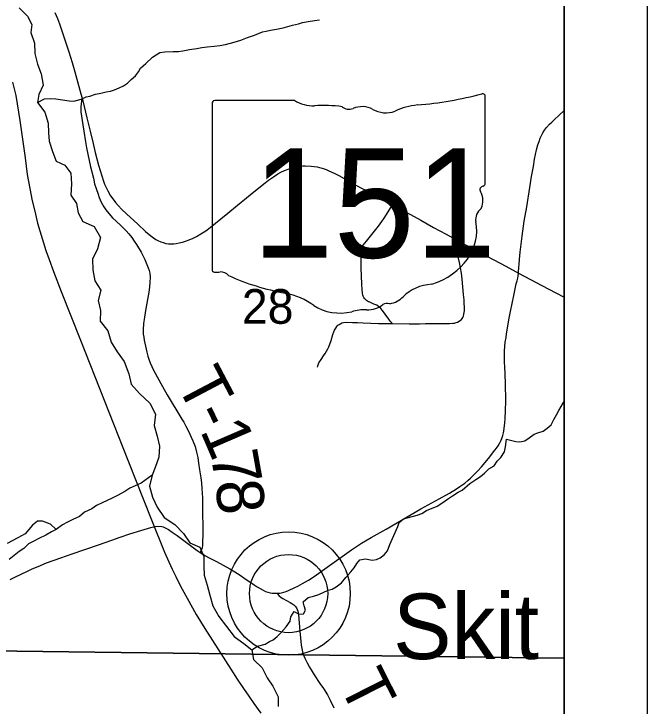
# Model space of a CAD drawing. Extents: x 0 to 34, y 0 to 22.
# Drawn here: x 16.736 to 17.5, y 15.839 to 16.673 of the extents above; entities that cross this region are included whole.
import ezdxf

# ---------------------------------------------------------------- set-up
doc = ezdxf.new("R2010")
doc.units = 0
for name, color, linetype in [('GM_X_Corporation', 7, 'Continuous'), ('GM_X_County_Road', 7, 'Continuous'), ('GM_X_Major_River', 7, 'Continuous'), ('GM_X_Minor_River', 7, 'Continuous'), ('GM_X_Rail_Line', 7, 'Continuous'), ('GM_X_Section_Text', 7, 'Continuous'), ('GM_X_State_Location', 7, 'Continuous'), ('GM_X_State_Route', 7, 'Continuous'), ('GM_X_State_Shield', 7, 'Continuous'), ('GM_X_Township_Road', 7, 'Continuous'), ('GM_X_Township_Road_Text', 7, 'Continuous'), ('GM_X_Unincorporated', 7, 'Continuous'), ('GM_X_Unincorporated_Location', 7, 'Continuous'), ('GM_X_Unincorporated_Text', 7, 'Continuous'), ('SH_Data', 7, 'Continuous')]:
    doc.layers.add(name, color=color, linetype=linetype)

msp = doc.modelspace()

# ---------------------------------------------------------------- linework, layer by layer
at = {"layer": 'GM_X_Corporation'}
for points in [[(16.42143, 13.6), (17.4, 13.6), (17.4, 16.91301), (16.55155, 16.92431), (16.46891, 16.92454), (16.46029, 16.26174), (16.46108, 16.1288), (16.45161, 15.59641), (16.44975, 15.46263), (16.44192, 14.8642), (16.438, 14.59078), (16.43392, 14.38059), (16.42123, 13.66087)], [(17.4, 15.89665), (17.4, 16.91338), (16.46597, 16.92627), (16.46598, 16.92141), (16.45629, 15.90843)], [(17.4, 14.8906), (17.4, 15.89665), (16.45629, 15.90843), (16.44101, 14.88556)]]:
    msp.add_lwpolyline(points, close=True, dxfattribs=at)
at = {"layer": 'GM_X_County_Road'}
for points in [[(17.34462, 16.36077), (17.3448, 16.36271), (17.3452, 16.36697), (17.34553, 16.37175), (17.34603, 16.37726), (17.34673, 16.38598), (17.34906, 16.40527), (17.3518, 16.42351), (17.35476, 16.44079), (17.3584, 16.46396), (17.36055, 16.4773), (17.3627, 16.48912), (17.36409, 16.49806), (17.36646, 16.5094), (17.36821, 16.51528), (17.36953, 16.5195), (17.37106, 16.52334), (17.37251, 16.5265), (17.37427, 16.52968), (17.37631, 16.53292), (17.37861, 16.5361), (17.38215, 16.54011), (17.38492, 16.54288), (17.38769, 16.54558), (17.4, 16.55658)], [(17.05349, 15.97466), (17.05498, 15.97474), (17.05687, 15.97497), (17.05903, 15.97539), (17.0644, 15.97698), (17.06744, 15.97813), (17.07505, 15.98153), (17.07873, 15.98341), (17.08438, 15.98651), (17.09128, 15.99057), (17.09931, 15.99567), (17.10566, 16.00001), (17.11698, 16.00818), (17.14334, 16.02718), (17.15545, 16.03493), (17.16698, 16.04194), (17.18507, 16.05219), (17.22703, 16.07633), (17.24891, 16.08843), (17.26161, 16.09551), (17.27017, 16.1007), (17.2742, 16.10335), (17.27641, 16.10489), (17.28008, 16.10758), (17.2837, 16.1106), (17.28688, 16.11341), (17.2927, 16.11913), (17.29587, 16.12248), (17.30016, 16.12713), (17.30861, 16.13738), (17.31643, 16.14712), (17.31823, 16.14948), (17.32025, 16.15256), (17.3223, 16.15595), (17.32349, 16.1585), (17.32479, 16.16135), (17.32605, 16.16499), (17.32683, 16.16819), (17.32722, 16.17026), (17.3284, 16.18022), (17.32878, 16.18499), (17.32911, 16.19492), (17.32935, 16.20626), (17.32899, 16.22808), (17.32824, 16.24832), (17.32803, 16.25262), (17.32793, 16.25808), (17.32804, 16.26716), (17.3289, 16.27733), (17.32981, 16.28323), (17.33048, 16.28743), (17.33368, 16.30637), (17.33529, 16.31457), (17.33909, 16.33381), (17.34197, 16.34768), (17.34316, 16.35155), (17.34387, 16.35459), (17.34432, 16.3572), (17.34462, 16.36077)], [(16.73158, 15.99118), (16.73726, 15.99418), (16.75247, 16.00142), (16.75828, 16.00404), (16.76524, 16.0071), (16.77542, 16.01127), (16.79256, 16.0175), (16.80652, 16.02237), (16.8383, 16.03328), (16.85401, 16.03884), (16.86434, 16.04243), (16.87598, 16.04633), (16.88926, 16.05056), (16.9013, 16.05406), (16.90636, 16.05514), (16.90943, 16.05552), (16.91468, 16.05518), (16.91617, 16.05465), (16.91779, 16.05398), (16.9203, 16.05278), (16.92265, 16.05141), (16.92709, 16.04848), (16.93295, 16.04418), (16.9556, 16.02743), (16.9584, 16.02551), (16.96087, 16.02387)], [(16.96087, 16.02387), (16.9671, 16.01997), (16.97099, 16.01781), (16.98036, 16.01284), (16.99651, 16.00427), (17.00277, 16.0006), (17.00885, 15.99668), (17.01347, 15.99351), (17.02572, 15.9848), (17.02936, 15.98259), (17.03305, 15.98039), (17.03668, 15.97844), (17.03966, 15.97703), (17.04236, 15.97604), (17.04511, 15.97536), (17.04753, 15.97498), (17.05156, 15.97467), (17.05349, 15.97466)]]:
    msp.add_lwpolyline(points, dxfattribs=at)
at = {"layer": 'GM_X_Major_River'}
for points in [[(16.74262, 16.68064), (16.75263, 16.67053), (16.7577, 16.66036), (16.7563, 16.65085), (16.76103, 16.63801), (16.76119, 16.62549), (16.7644, 16.61263), (16.76911, 16.60093), (16.77156, 16.58731), (16.76602, 16.57585), (16.76463, 16.56634), (16.77351, 16.5547), (16.77748, 16.54147), (16.77764, 16.52971), (16.77852, 16.51985), (16.78249, 16.50739), (16.78719, 16.49569), (16.79751, 16.49089), (16.80485, 16.48113), (16.8054, 16.46823), (16.80482, 16.45456), (16.81178, 16.44479), (16.81345, 16.43343), (16.81928, 16.42288), (16.83303, 16.417), (16.84041, 16.40382), (16.8368, 16.39011), (16.83089, 16.3775), (16.83144, 16.36461), (16.83389, 16.35136), (16.84087, 16.34007), (16.83762, 16.3275), (16.84043, 16.31578), (16.84022, 16.30287), (16.84949, 16.29123), (16.85346, 16.27762), (16.86083, 16.26596), (16.86895, 16.25431), (16.87484, 16.23921), (16.87767, 16.22672), (16.88768, 16.21547), (16.89998, 16.20388), (16.90699, 16.19069), (16.90527, 16.177), (16.90886, 16.16415)], [(16.90886, 16.16415), (16.91167, 16.15204), (16.91071, 16.13875), (16.90631, 16.12654), (16.90302, 16.11701), (16.89978, 16.10368), (16.90337, 16.09045), (16.90884, 16.07838), (16.91735, 16.06597), (16.93037, 16.05742), (16.94076, 16.04693), (16.9485, 16.03565), (16.96034, 16.03012), (16.96504, 16.01918), (16.9652, 16.00742), (16.96572, 15.99642), (16.96929, 15.98432), (16.97248, 15.9726), (16.97607, 15.95974), (16.98345, 15.94656), (16.99234, 15.93453), (17.00161, 15.92252), (17.01349, 15.91395), (17.02308, 15.90649), (17.02513, 15.89475), (17.03551, 15.88464), (17.04175, 15.87258), (17.04833, 15.8628), (17.05495, 15.84999), (17.05472, 15.83822)]]:
    msp.add_lwpolyline(points, dxfattribs=at)
at = {"layer": 'GM_X_Minor_River'}
for points in [[(16.76463, 16.56634), (16.77318, 16.57094), (16.78075, 16.57107), (16.78682, 16.5708), (16.7948, 16.5698), (16.80278, 16.56842), (16.80847, 16.56813), (16.81715, 16.57056), (16.82317, 16.57332), (16.8277, 16.57416), (16.83448, 16.57656), (16.8409, 16.57781), (16.84732, 16.57944), (16.85262, 16.57991), (16.85752, 16.58152), (16.86316, 16.58389), (16.86842, 16.58664), (16.87292, 16.58976), (16.8774, 16.59402), (16.88262, 16.59867), (16.88633, 16.60329), (16.88891, 16.60789), (16.89526, 16.61332), (16.90309, 16.62105), (16.91209, 16.62652), (16.91814, 16.62739), (16.92837, 16.62795), (16.93443, 16.62805), (16.93973, 16.62852), (16.94804, 16.63018), (16.95673, 16.63147), (16.96278, 16.63272), (16.96921, 16.63359), (16.97753, 16.63449), (16.98434, 16.63499), (16.99114, 16.63624), (17.00171, 16.63909), (17.00963, 16.6415), (17.01791, 16.64468), (17.0262, 16.64749), (17.03599, 16.65145), (17.04052, 16.65229), (17.04543, 16.65351), (17.05299, 16.65478), (17.06092, 16.65644), (17.07224, 16.65967), (17.07941, 16.66132), (17.08431, 16.66292), (17.09111, 16.66418), (17.09867, 16.66545), (17.10473, 16.66593)], [(17.02308, 15.90649), (17.02996, 15.9109), (17.03901, 15.91333), (17.04427, 15.91646), (17.04878, 15.91844), (17.05364, 15.9227), (17.05849, 15.92735), (17.06443, 15.93429), (17.06924, 15.94121), (17.0703, 15.94616), (17.07398, 15.95269), (17.07972, 15.94937), (17.08539, 15.94984), (17.08797, 15.95445), (17.08637, 15.95936), (17.08515, 15.96428), (17.09112, 15.9697), (17.09754, 15.97133), (17.10395, 15.97334), (17.11523, 15.97847), (17.12014, 15.97969), (17.12502, 15.98244), (17.13138, 15.98749), (17.13658, 15.99365), (17.14253, 16.0006), (17.14662, 16.00522), (17.14994, 16.0106), (17.15327, 16.01521), (17.16008, 16.01609), (17.16806, 16.01471), (17.17335, 16.01556), (17.17787, 16.01754), (17.18274, 16.02104), (17.18682, 16.02605), (17.18973, 16.03332), (17.19447, 16.04442), (17.19922, 16.05514), (17.20103, 16.06011), (17.20588, 16.06437), (17.22248, 16.06883), (17.22814, 16.07083), (17.23376, 16.07434), (17.24655, 16.07988), (17.25368, 16.08418), (17.2593, 16.08808), (17.2653, 16.09198), (17.27204, 16.09665), (17.27693, 16.09902), (17.28627, 16.10716), (17.29339, 16.11184), (17.29902, 16.11535), (17.30387, 16.11961), (17.3091, 16.12464), (17.31547, 16.12855), (17.31917, 16.13393), (17.32364, 16.13857), (17.32808, 16.1451), (17.32911, 16.1512), (17.33047, 16.16034), (17.33656, 16.15892), (17.34151, 16.15749), (17.34645, 16.15719), (17.35249, 16.15844), (17.35774, 16.16195), (17.36372, 16.16661), (17.36824, 16.16821), (17.37465, 16.17021), (17.37952, 16.17372), (17.384, 16.17797), (17.38731, 16.18411), (17.39062, 16.18986), (17.39356, 16.19523), (17.39614, 16.19983), (17.39908, 16.20482), (17.4, 16.20592)], [(16.90302, 16.11701), (16.88943, 16.10757), (16.88228, 16.10441), (16.87589, 16.10126), (16.8699, 16.09735), (16.86201, 16.09304), (16.85449, 16.08949), (16.84847, 16.08673), (16.84246, 16.08359), (16.83569, 16.08043), (16.83007, 16.07653), (16.82142, 16.07259), (16.81507, 16.06716), (16.80717, 16.0636), (16.80078, 16.06045), (16.79477, 16.05731), (16.78691, 16.05148), (16.78127, 16.04872), (16.77452, 16.0448), (16.76624, 16.04086), (16.76024, 16.03734), (16.75385, 16.03419), (16.74788, 16.02877), (16.74226, 16.02487), (16.73029, 16.01555)], [(16.78691, 16.05148), (16.78035, 16.0582), (16.77044, 16.06183), (16.76437, 16.06173), (16.7584, 16.05668), (16.74947, 16.04627), (16.74084, 16.04156), (16.72806, 16.03489)]]:
    msp.add_lwpolyline(points, dxfattribs=at)
at = {"layer": 'GM_X_Rail_Line'}
msp.add_lwpolyline([(16.73436, 16.59103), (16.73822, 16.57482), (16.74336, 16.54454), (16.74948, 16.49966), (16.75226, 16.47959), (16.75519, 16.46261), (16.75828, 16.4478), (16.76121, 16.43529), (16.76461, 16.42079), (16.77188, 16.39736), (16.77464, 16.38791), (16.7785, 16.37726), (16.78375, 16.3626), (16.79316, 16.33852), (16.81632, 16.27971), (16.87358, 16.13509), (16.90213, 16.06317), (16.91772, 16.02427), (16.92281, 16.01269), (16.92698, 16.0039), (16.9313, 15.99479), (16.93701, 15.98337), (16.94489, 15.96871), (16.956, 15.94926), (16.96634, 15.93243), (16.99783, 15.88335), (17.00539, 15.87116), (17.01295, 15.86005), (17.01944, 15.85063), (17.02561, 15.84168), (17.0341, 15.83026)], dxfattribs=at)
at = {"layer": 'GM_X_State_Route'}
msp.add_lwpolyline([(16.78541, 16.67497), (16.78848, 16.6675), (16.7909, 16.66117), (16.79424, 16.65172), (16.80222, 16.62758), (16.80634, 16.61453), (16.8096, 16.60343), (16.81697, 16.57671), (16.81835, 16.57147), (16.82091, 16.56151), (16.82424, 16.548), (16.82818, 16.53171), (16.83163, 16.51694), (16.83422, 16.50627), (16.83817, 16.49073), (16.84009, 16.48428), (16.8441, 16.47154), (16.84553, 16.46797), (16.84805, 16.46235), (16.84933, 16.45994), (16.85278, 16.45404), (16.85537, 16.45011), (16.85854, 16.44591), (16.86183, 16.44221), (16.86633, 16.43747), (16.87197, 16.43221), (16.88563, 16.41955), (16.895, 16.41092), (16.90121, 16.40562), (16.90431, 16.40319), (16.90744, 16.40113), (16.90986, 16.39983), (16.91313, 16.3984), (16.91596, 16.39741), (16.91939, 16.39654), (16.92248, 16.3961), (16.9259, 16.39594), (16.92909, 16.39605), (16.93189, 16.39638), (16.93534, 16.39702), (16.93948, 16.39801), (16.94325, 16.39913), (16.94744, 16.40068), (16.95233, 16.40286), (16.95646, 16.40498), (16.96176, 16.40807), (16.96744, 16.4116), (16.97275, 16.41553), (16.98577, 16.42606), (16.99412, 16.43299), (17.00598, 16.44274), (17.01663, 16.45152), (17.02542, 16.45889), (17.03935, 16.4697), (17.04328, 16.47263), (17.04904, 16.47671), (17.05461, 16.48026), (17.05814, 16.48224), (17.06244, 16.48429), (17.06706, 16.48614), (17.07132, 16.48751), (17.07516, 16.48845), (17.07956, 16.4893), (17.08476, 16.48994), (17.08758, 16.49008), (17.09477, 16.4898), (17.10191, 16.48873), (17.10477, 16.48809), (17.10813, 16.48713), (17.11292, 16.48548), (17.11617, 16.48416), (17.12231, 16.48132), (17.12905, 16.47781), (17.13946, 16.47215), (17.15391, 16.46401), (17.16865, 16.45615), (17.19253, 16.44306), (17.20597, 16.43585), (17.21437, 16.43135), (17.22701, 16.42443), (17.2423, 16.41584), (17.25737, 16.40764), (17.27424, 16.39848), (17.2755, 16.39781), (17.3049, 16.382), (17.31508, 16.37656), (17.32934, 16.36896), (17.34462, 16.36077), (17.38054, 16.3419), (17.4, 16.33154)], dxfattribs=at)
at = {"layer": 'GM_X_State_Shield'}
for p, q in [((17.07492, 16.56875), (16.9784, 16.56875)), ((17.30474, 16.46903), (17.30474, 16.57371)), ((16.97516, 16.56531), (16.97516, 16.36519)), ((17.30471, 16.46905), (17.30474, 16.46903))]:
    msp.add_line(p, q, dxfattribs=at)
for centre, major_axis, start_param, end_param in [((17.18734, 16.84158), (0.34952, 0), 4.814394, 5.042369), ((17.30109, 16.57414), (0.00367, 0), 6.141152, 7.989035), ((16.97893, 16.56573), (0.00382, 0), 1.712693, 3.28349), ((17.09791, 16.59198), (0.03703, 0), 4.042523, 4.731795), ((17.11019, 16.4564), (0.13295, 0), 1.404758, 1.657858), ((17.14037, 16.56677), (0.01068, 0), 3.836095, 5.185415), ((17.15606, 16.54364), (0.02221, 0), 0.950623, 2.079405), ((17.23192, 16.50763), (0.07032, 0), 1.699011, 2.107814), ((17.18473, 16.57537), (0.02672, 0), 4.081561, 5.145723), ((17.30083, 16.46862), (0.00393, 0), 5.05454, 6.418171), ((17.30389, 16.46134), (0.00568, 0), 1.883978, 3.671073), ((17.26777, 16.44811), (0.03409, 0), 5.934695, 6.695948), ((17.31789, 16.42522), (0.0248, 0), 2.387724, 3.262537), ((17.20692, 16.4119), (0.08742, 0), 5.101752, 6.440018), ((16.97897, 16.36475), (0.00385, 0), 3.00124, 4.508301), ((16.97955, 16.38522), (0.0294, 0), 4.665946, 4.897461), ((16.98557, 16.35364), (0.0106, 0), 0.519207, 1.627899), ((17.11939, 16.53344), (0.2524, 0), 4.195997, 4.488961), ((17.24378, 16.309), (0.04788, 0), 1.647645, 2.488434), ((17.04414, 16.27528), (0.07897, 0), 0.823519, 1.323587), ((17.18312, 16.34579), (0.02824, 0), 4.937069, 5.64225), ((17.12955, 16.35265), (0.05011, 0), 4.026481, 4.996735), ((17.16217, 16.33766), (0.0267, 0), 4.691044, 5.507374), ((17.18632, 16.31828), (0.00752, 0), 1.147584, 2.315152), ((17.15851, 16.28346), (0.04118, 0), 1.495662, 1.94098)]:
    msp.add_ellipse(centre, major_axis=major_axis, ratio=0.8, start_param=start_param, end_param=end_param, dxfattribs=at)
at = {"layer": 'GM_X_Township_Road'}
for points in [[(16.81835, 16.57147), (16.81781, 16.56968), (16.81744, 16.56747), (16.81707, 16.56524), (16.81666, 16.56087), (16.81699, 16.55527), (16.81922, 16.5396), (16.82051, 16.53181), (16.82248, 16.51899), (16.82378, 16.51158), (16.82848, 16.48879), (16.83189, 16.47507), (16.83348, 16.46851), (16.83512, 16.46285), (16.83756, 16.45577), (16.83893, 16.45177), (16.84127, 16.44628), (16.84453, 16.44068), (16.84682, 16.43698), (16.85042, 16.4326), (16.85512, 16.42749), (16.86469, 16.41845), (16.87157, 16.41182), (16.87472, 16.40821), (16.87819, 16.4038), (16.8813, 16.3994), (16.88397, 16.39528), (16.88955, 16.38589), (16.89202, 16.38129), (16.8941, 16.37697), (16.89571, 16.37311), (16.8982, 16.36691), (16.89913, 16.36399), (16.89995, 16.36058), (16.90044, 16.35555), (16.90021, 16.34972), (16.89958, 16.34357), (16.89868, 16.33771), (16.89489, 16.3155), (16.89316, 16.30474), (16.8925, 16.29993), (16.89188, 16.29222), (16.89214, 16.2869), (16.89263, 16.28346), (16.89333, 16.27974), (16.89647, 16.2654), (16.89771, 16.26069), (16.89891, 16.2569), (16.90064, 16.25239), (16.90258, 16.24801), (16.9046, 16.24376), (16.91522, 16.22418), (16.92105, 16.21399), (16.93854, 16.18461), (16.94091, 16.18099), (16.94348, 16.17615), (16.94615, 16.17086), (16.95188, 16.15836), (16.9548, 16.15149), (16.95653, 16.14482), (16.95791, 16.1383), (16.9589, 16.13167), (16.96013, 16.12372), (16.96161, 16.11387), (16.96227, 16.10804), (16.9628, 16.10094), (16.96339, 16.08958), (16.96359, 16.07742), (16.96404, 16.04926), (16.9637, 16.03259), (16.96301, 16.02964), (16.96232, 16.02746), (16.96087, 16.02387)], [(17.19258, 16.29982), (17.19152, 16.30099), (17.18993, 16.30291), (17.18825, 16.30512), (17.18401, 16.31121), (17.1807, 16.31578), (17.17878, 16.3179), (17.17637, 16.32015), (17.17375, 16.32187), (17.17045, 16.32346), (17.16534, 16.3255), (17.16378, 16.32616), (17.16264, 16.32681), (17.1615, 16.32767), (17.16047, 16.32859), (17.15917, 16.32994), (17.1581, 16.33139), (17.15741, 16.33277), (17.15692, 16.33425), (17.15647, 16.33666), (17.15605, 16.34112), (17.15574, 16.34718), (17.15517, 16.36722), (17.1551, 16.38448), (17.15521, 16.38731), (17.15551, 16.38985), (17.15639, 16.39234), (17.15745, 16.39421), (17.16129, 16.39912), (17.17602, 16.41746), (17.17996, 16.42281), (17.18285, 16.42691), (17.18764, 16.43478), (17.19071, 16.43987), (17.19253, 16.44306)], [(17.10233, 16.24737), (17.10283, 16.24908), (17.10408, 16.25234), (17.10664, 16.25674), (17.10964, 16.26092), (17.11156, 16.26371), (17.11487, 16.26942), (17.11607, 16.27198), (17.11868, 16.2794), (17.12081, 16.2867), (17.12193, 16.28987), (17.12297, 16.29209), (17.12423, 16.29427), (17.12569, 16.29641), (17.12697, 16.29775), (17.12848, 16.29892), (17.13027, 16.3), (17.13175, 16.30067), (17.13349, 16.30116), (17.13709, 16.30145), (17.14438, 16.30136), (17.1506, 16.30099), (17.15748, 16.30061), (17.17582, 16.3001), (17.19258, 16.29982), (17.21298, 16.29969), (17.22541, 16.29975), (17.23268, 16.29985), (17.24467, 16.29991), (17.26142, 16.30007), (17.2654, 16.30027), (17.26776, 16.30054), (17.26967, 16.30102), (17.27132, 16.30166), (17.27341, 16.30278), (17.27495, 16.30387), (17.2759, 16.30481), (17.27669, 16.30584), (17.27749, 16.30707), (17.27831, 16.30871), (17.27901, 16.31101), (17.27948, 16.31518), (17.27906, 16.32831), (17.27858, 16.33481), (17.27677, 16.35328), (17.27587, 16.36059), (17.27356, 16.37352), (17.2724, 16.37887), (17.27178, 16.38417), (17.27166, 16.38726), (17.27189, 16.38948), (17.27288, 16.39247), (17.27414, 16.39512), (17.2755, 16.39781)], [(16.96087, 16.02387), (16.9671, 16.01997), (16.97099, 16.01781), (16.98036, 16.01284), (16.99651, 16.00427), (17.00277, 16.0006), (17.00885, 15.99668), (17.01347, 15.99351), (17.02572, 15.9848), (17.02936, 15.98259), (17.03305, 15.98039), (17.03668, 15.97844), (17.03966, 15.97703), (17.04236, 15.97604), (17.04511, 15.97536), (17.04753, 15.97498), (17.05156, 15.97467), (17.05349, 15.97466)], [(17.05349, 15.97466), (17.05404, 15.9739), (17.05567, 15.97207), (17.05851, 15.96976), (17.06052, 15.96855), (17.06925, 15.96373), (17.07145, 15.96238), (17.07367, 15.96061), (17.07535, 15.95896), (17.07679, 15.95711), (17.07782, 15.95532), (17.07868, 15.95329), (17.07917, 15.95129), (17.0795, 15.94904), (17.08108, 15.92865), (17.08203, 15.91697), (17.08265, 15.91201), (17.08364, 15.90608), (17.08476, 15.90223), (17.08701, 15.89639), (17.08972, 15.89096), (17.0925, 15.88572), (17.09583, 15.88034), (17.09826, 15.8765), (17.10516, 15.86611), (17.10966, 15.85984), (17.11445, 15.85244), (17.11766, 15.84594), (17.12197, 15.83677)]]:
    msp.add_lwpolyline(points, dxfattribs=at)
at = {"layer": 'GM_X_Unincorporated'}
for radius in [0.0744, 0.04716]:
    msp.add_circle((17.06746, 15.97431), radius, dxfattribs=at)
at = {"layer": 'GM_X_Unincorporated_Location'}
msp.add_line((17.06746, 15.97431), (17.06746, 15.97431), dxfattribs=at)
at = {"layer": 'SH_Data'}
for points in [[(10.5, 20.5), (17.5, 20.5), (17.5, 13.5), (10.5, 13.5)], [(10.6, 20.4), (17.4, 20.4), (17.4, 13.6), (10.6, 13.6)]]:
    msp.add_lwpolyline(points, close=True, dxfattribs=at)

# ---------------------------------------------------------------- texts
at = {"layer": 'GM_X_Section_Text'}
msp.add_text('28', height=0.041856, rotation=0.00001, dxfattribs=at).set_placement((17.01105, 16.29961))
at = {"layer": 'GM_X_State_Location'}
for s, p in [('s', (17.13625, 16.45194)), ('r', (17.13624, 16.45194))]:
    msp.add_text(s, height=0.000189, dxfattribs=at).set_placement(p)
msp.add_text('151', height=0.000189, rotation=0.00001, dxfattribs=at).set_placement((17.06939, 16.43816))
at = {"layer": 'GM_X_State_Shield'}
msp.add_text('151', height=0.131836, dxfattribs=at).set_placement((17.02372, 16.3793))
at = {"layer": 'GM_X_Township_Road_Text'}
for s, rotation, p in [('T', 297.8127, (16.93083, 16.22834)), ('-', 295.92561, (16.95039, 16.19126)), ('1', 293.33318, (16.96022, 16.17108)), ('7', 280.1357, (16.97298, 16.14251)), ('8', 275.91115, (16.97894, 16.10942)), ('T', 296.80411, (17.12722, 15.86529))]:
    msp.add_text(s, height=0.05682, rotation=rotation, dxfattribs=at).set_placement(p)
at = {"layer": 'GM_X_Unincorporated_Text'}
msp.add_text('Skit', height=0.078977, rotation=0.00001, dxfattribs=at).set_placement((17.19355, 15.89534))

doc.saveas('drawing.dxf')
